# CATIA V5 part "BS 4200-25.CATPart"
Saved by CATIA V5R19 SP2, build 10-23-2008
Part number: BS 4200-25
Bounding box of the stored display mesh (mm): x -47.487 to 47.487, y -47.487 to 47.487, z 0 to 115
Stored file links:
  C:\Users\Bora\Desktop\3D Katı model\BS serisi\BS 4200\BS 4200-25.CATPart
  C:\Program Files\Dassault Systemes\B19\intel_a\reffiles\standard\MetricThickPitch.txt
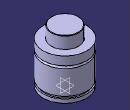
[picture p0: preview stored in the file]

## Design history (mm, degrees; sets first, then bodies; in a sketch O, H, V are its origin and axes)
Body1 (main body)
  Sketch1 on yz-plane, origin (0, 0, 0), H (0, 1, 0), V (0, 0, 1)
    point P2 (47.5, 65.5)
    point P5 (30, 114)
    point P7 (30, 114)
    point P11 (47.5, 70.5)
    point P13 (47.5, 70.5)
    point P14 (47.5, 65.5)
    line L1 (47.5, 13) -> (47.5, 65.5)
    line L2 (44.5, 13) -> (44.5, 8)
    line L3 (30, 114) -> (30, 89)
    arc A1 centre (29, 114) radius 1 from (30, 114) to (29, 115) ccw
    line L4 (47.5, 0) -> (47.5, 8)
    line L5 (47.5, 70.5) -> (47.5, 89)
    arc A2 centre (47.5, 68) radius 2.5 from (47.5, 70.5) to (47.5, 65.5) ccw
    line L6 (29, 115) -> (0, 115)
    point P15 (0, 115)
    line L7 (30, 89) -> (47.5, 89)
    line L8 (0, 0) -> (47.5, 0)
    line L9 (44.5, 13) -> (47.5, 13)
    line L10 (44.5, 8) -> (47.5, 8)
    coincidence: P15 V, P2 P14, P5 P7, P11 P13
    tangency: L6 A1
    horizontal: L7 H, L8 H, L9 H, L10 H
  Shaft1: profile Sketch1, axis Sketch1.V, angle 360
  Sketch2 on face of Shaft1 from Sketch1.L8, origin (0, 0, 0), H (1, 0, 0), V (0, -1, 0)
    point P1 (30, 0)
    distance P1 V = 30
  Hole1: placed by Sketch2, at (30, 0, 0) direction (0, 0, 1), diameter 6.647, depth 7, threaded "M8", thread diameter 8, thread depth 7, pitch 1.25
  CircPattern1: of Hole1, instances 4, angular step 90, axis from xy-plane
